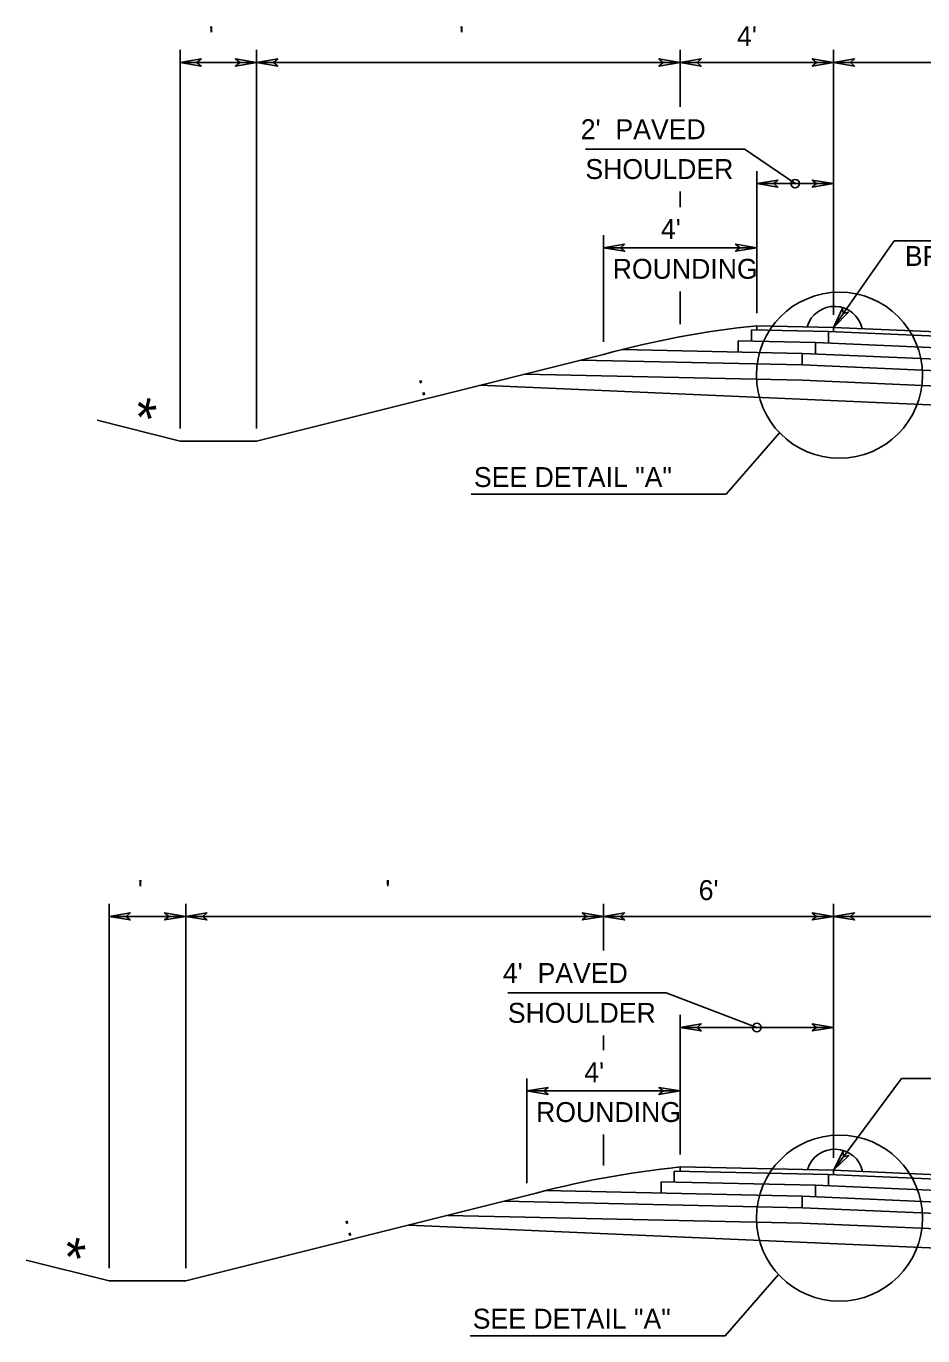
# Model space of a CAD drawing. Extents: x -592 to 1199, y -590 to 416.
# Drawn here: x 460.9 to 524, y -200.2 to -108.2 of the extents above; entities that cross this region are included whole.
import ezdxf

# ---------------------------------------------------------------- set-up
doc = ezdxf.new("R2010")
doc.units = 0
doc.layers.add('1', color=7, linetype='Continuous')
doc.layers.add('Des_ Drain_ Ftrs', color=7, linetype='Continuous')

msp = doc.modelspace()

# ---------------------------------------------------------------- linework, layer by layer
at = {"layer": '1'}
for p, q in [((471.74, -136.465), (471.74, -109.853)), ((477.129, -136.465), (477.129, -109.853)), ((506.9, -113.851), (506.9, -109.853)), ((517.677, -128.476), (517.677, -109.853)), ((477.129, -110.733), (471.74, -110.733)), ((506.9, -110.733), (477.129, -110.733)), ((517.677, -110.733), (506.9, -110.733)), ((544.618, -110.733), (517.677, -110.733)), ((500.24, -116.824), (511.381, -116.824)), ((514.982, -119.249), (511.396, -116.803)), ((512.288, -128.359), (512.288, -118.369)), ((517.677, -119.249), (512.288, -119.249)), ((506.9, -120.913), (506.9, -119.804)), ((501.512, -130.369), (501.512, -122.873)), ((517.67, -129.356), (521.952, -123.267)), ((535.9, -123.267), (521.952, -123.267)), ((512.288, -123.753), (501.512, -123.753)), ((506.9, -129.137), (506.9, -126.822)), ((511.911, -129.531), (517.331, -129.641)), ((511.911, -130.312), (511.911, -129.531)), ((512.288, -129.239), (517.67, -129.356)), ((512.288, -129.239), (512.288, -129.539)), ((544.618, -130.833), (517.331, -129.641)), ((517.331, -130.451), (517.331, -129.641)), ((544.618, -130.533), (517.67, -129.356)), ((517.67, -129.356), (517.67, -129.656)), ((510.985, -130.292), (516.408, -130.41)), ((510.985, -131.081), (510.985, -130.292)), ((544.618, -131.642), (516.408, -130.41)), ((516.408, -131.22), (516.408, -130.41)), ((501.512, -131.249), (477.129, -137.345)), ((502.835, -130.903), (515.486, -131.179)), ((544.618, -132.451), (515.486, -131.179)), ((515.486, -131.988), (515.486, -131.179)), ((499.916, -131.648), (515.486, -131.988)), ((544.618, -133.26), (515.486, -131.988)), ((544.618, -135.687), (492.811, -133.425)), ((495.949, -132.64), (515.486, -133.067)), ((544.618, -134.339), (515.486, -133.067)), ((465.913, -135.888), (471.74, -137.345)), ((510.147, -141.079), (513.887, -136.759)), ((477.129, -137.345), (471.74, -137.345)), ((492.216, -141.079), (510.147, -141.079)), ((466.754, -195.499), (466.754, -169.88)), ((472.142, -195.499), (472.142, -169.88)), ((501.512, -173.164), (501.512, -169.88)), ((517.677, -187.728), (517.677, -169.88)), ((472.142, -170.76), (466.754, -170.76)), ((501.512, -170.76), (472.142, -170.76)), ((517.677, -170.76), (501.512, -170.76)), ((544.618, -170.76), (517.677, -170.76)), ((494.786, -176.141), (505.927, -176.141)), ((512.288, -178.566), (505.927, -176.141)), ((506.9, -187.493), (506.9, -177.686)), ((517.677, -178.566), (506.9, -178.566)), ((501.512, -180.174), (501.512, -179.121)), ((496.124, -189.504), (496.124, -182.149)), ((517.67, -188.608), (522.462, -182.155)), ((535.937, -182.155), (522.462, -182.155)), ((506.9, -183.029), (496.124, -183.029)), ((501.512, -188.27), (501.512, -186.087)), ((506.484, -188.664), (517.331, -188.893)), ((506.484, -189.445), (506.484, -188.664)), ((506.9, -188.373), (517.67, -188.608)), ((506.9, -188.373), (506.9, -188.673)), ((544.618, -189.784), (517.67, -188.608)), ((517.67, -188.908), (517.67, -188.608)), ((505.558, -189.425), (516.408, -189.662)), ((505.558, -190.214), (505.558, -189.425)), ((544.618, -190.084), (517.331, -188.893)), ((517.331, -189.702), (517.331, -188.893)), ((496.124, -190.383), (472.142, -196.379)), ((497.448, -190.037), (515.486, -190.431)), ((544.618, -191.703), (515.486, -190.431)), ((515.486, -191.241), (515.486, -190.431)), ((544.618, -190.894), (516.408, -189.662)), ((516.408, -190.471), (516.408, -189.662)), ((494.527, -190.783), (515.501, -191.241)), ((544.618, -192.512), (515.501, -191.241)), ((490.562, -191.774), (515.486, -192.318)), ((544.618, -193.59), (515.486, -192.318)), ((544.618, -194.939), (487.824, -192.458)), ((460.926, -194.922), (466.754, -196.379)), ((510.064, -200.242), (513.804, -195.923)), ((472.142, -196.379), (466.754, -196.379)), ((492.132, -200.242), (510.064, -200.242))]:
    msp.add_line(p, q, dxfattribs=at)
for centre, radius in [((514.982, -119.249), 0.3), ((518.097, -132.715), 5.838), ((512.288, -178.566), 0.3), ((518.097, -191.967), 5.838)]:
    msp.add_circle(centre, radius, dxfattribs=at)
for centre, radius, start, end in [((517.748, -129.87), 1.995, 12.28521, 163.88489), ((519.183, -196.074), 67.19, 95.89012, 105.24869), ((517.777, -189.111), 1.994, 11.96264, 164.17161), ((513.796, -255.206), 67.188, 95.89109, 105.24966)]:
    msp.add_arc(centre, radius, start, end, dxfattribs=at)
at = {"layer": 'Des_ Drain_ Ftrs'}
for points in [[(471.74, -110.733), (473.229, -110.981), (472.934, -110.733), (473.229, -110.485)], [(477.129, -110.733), (475.64, -110.981), (475.935, -110.733), (475.64, -110.485)], [(477.129, -110.733), (478.617, -110.981), (478.322, -110.733), (478.617, -110.485)], [(506.9, -110.733), (505.412, -110.981), (505.707, -110.733), (505.412, -110.485)], [(506.9, -110.733), (508.388, -110.981), (508.093, -110.733), (508.388, -110.485)], [(517.677, -110.733), (516.188, -110.981), (516.483, -110.733), (516.188, -110.485)], [(517.677, -110.733), (519.165, -110.981), (518.87, -110.733), (519.165, -110.485)], [(512.288, -119.249), (513.777, -119.497), (513.482, -119.249), (513.777, -119.001)], [(517.677, -119.249), (516.188, -119.497), (516.483, -119.249), (516.188, -119.001)], [(501.512, -123.753), (503, -124.002), (502.705, -123.753), (503, -123.505)], [(512.288, -123.753), (510.8, -124.002), (511.095, -123.753), (510.8, -123.505)], [(517.67, -129.356), (518.729, -128.282), (518.357, -128.38), (518.323, -127.996)], [(466.754, -170.76), (468.242, -171.008), (467.947, -170.76), (468.242, -170.512)], [(472.142, -170.76), (470.653, -171.008), (470.948, -170.76), (470.653, -170.512)], [(472.142, -170.76), (473.63, -171.008), (473.335, -170.76), (473.63, -170.512)], [(501.512, -170.76), (500.024, -171.008), (500.319, -170.76), (500.024, -170.512)], [(501.512, -170.76), (503, -171.008), (502.705, -170.76), (503, -170.512)], [(517.677, -170.76), (516.188, -171.008), (516.483, -170.76), (516.188, -170.512)], [(517.677, -170.76), (519.165, -171.008), (518.87, -170.76), (519.165, -170.512)], [(506.9, -178.566), (508.388, -178.814), (508.093, -178.566), (508.388, -178.317)], [(517.677, -178.566), (516.188, -178.814), (516.483, -178.566), (516.188, -178.317)], [(496.124, -183.029), (497.612, -183.277), (497.317, -183.029), (497.612, -182.781)], [(506.9, -183.029), (505.412, -183.277), (505.707, -183.029), (505.412, -182.781)], [(517.67, -188.608), (518.757, -187.561), (518.382, -187.65), (518.358, -187.265)]]:
    msp.add_lwpolyline(points, close=True, dxfattribs=at)

# ---------------------------------------------------------------- texts
at = {"layer": '1'}
for s, p in [(" '", (473.239, -109.582)), ("  '", (490.318, -109.582)), ("4'", (510.898, -109.582)), ("2'  PAVED", (499.913, -116.124)), ('SHOULDER', (500.239, -118.924)), ("4'", (505.548, -123.138)), ('BREAKOVER', (522.697, -125.034)), ('ROUNDING', (502.159, -125.938)), ('SEE DETAIL "A"', (492.401, -140.576)), (" '", (468.253, -169.609)), ("  '", (485.131, -169.609)), ("6'", (508.204, -169.609)), ("4'  PAVED", (494.435, -175.441)), ('SHOULDER', (494.785, -178.241)), ("4'", (500.16, -182.413)), ('ROUNDING', (496.771, -185.213)), ('SEE DETAIL "A"', (492.318, -199.739))]:
    msp.add_text(s, height=1.4, dxfattribs=at).set_placement(p)
for s, height, rotation, p in [(' : ', 1.4, 14.22821, (488.14, -134.31)), ('*', 2.8, 347.15207, (468.226, -136.913)), (' : ', 1.4, 14.22821, (482.953, -193.394)), ('*', 2.8, 347.15207, (463.239, -195.947))]:
    msp.add_text(s, height=height, rotation=rotation, dxfattribs=at).set_placement(p)

doc.saveas('drawing.dxf')
